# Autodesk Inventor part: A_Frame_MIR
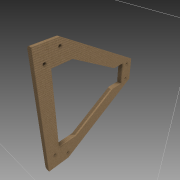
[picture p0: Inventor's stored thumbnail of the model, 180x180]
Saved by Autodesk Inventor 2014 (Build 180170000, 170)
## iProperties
Created: 2013-12
Part Number: A_Frame_MIR
Material: MDF Medium Density Fiberboard
Document SubType Name: Modeling
Designer: Bram
Density: 0.8 g/cm^3
Appearance: Cardboard - Corrugated
Author: Bram
d0: 7,800 ul
d2: 2,800 ul
d4: 4,625 ul
d6: 28,878 ul
d8: 33,300 ul
d10: 35,400 ul
d12: 37,800 ul
d14: 4,045 ul
d16: 2,900 ul
d18: 4,422 ul
d20: 2,400 ul
d22: 5,350 ul
d24: 13,950 ul
d26: 7,019 ul
d28: 21,250 ul
d30: 8,000 ul
d32: 7,300 ul
d34: 18,000 mm
d35: 0,00 deg
d36: 10,000 mm
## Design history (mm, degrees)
derived "A_Frame.ipt"
  sketch "Sketch1"
    geometry: L1 (-303.237, 40.135)-(-5.237, 212.185) reference; L2 (17.986, 139.185)-(-41.677, 139.185) reference; L3 (17.986, 139.185)-(28.513, 139.185) reference; L4 (28.513, 139.185)-(28.513, -0.315) reference; L5 (28.513, 212.185)-(-5.237, 212.185) reference; L6 (-5.237, 212.185)-(74.763, 212.185) reference; L7 (74.763, 212.185)-(74.763, -0.315) reference; L8 (-258.237, 39.685)-(-214.016, 39.685) reference; L9 (-214.016, 39.685)-(-41.677, 139.185) reference; L10 (-303.237, 40.135)-(-303.237, -0.315) reference; L11 (-258.237, 39.685)-(-258.237, -0.315) reference; L12 (-303.237, -40.764)-(-5.237, -212.815) reference; L13 (-214.016, -40.315)-(-41.677, -139.815) reference; L14 (28.513, -139.815)-(28.513, -0.315) reference; L15 (17.986, -139.815)-(-41.677, -139.815) reference; L16 (17.986, -139.815)-(28.513, -139.815) reference; L17 (28.513, -212.815)-(-5.237, -212.815) reference; L18 (-5.237, -212.815)-(74.763, -212.815) reference; L19 (74.763, -212.815)-(74.763, -0.315) reference; L20 (-258.237, -40.315)-(-214.016, -40.315) reference; L21 (-303.237, -40.764)-(-303.237, -0.315) reference; L22 (-258.237, -40.315)-(-258.237, -0.315) reference; L23 (28.513, 139.185)-(-41.677, 139.185) reference; L24 (-41.677, 139.185)-(-214.016, 39.685) reference; L25 (-214.016, 39.685)-(-258.237, 39.685) reference; L26 (-258.237, 39.685)-(-258.237, -40.315) reference; L27 (-258.237, -40.315)-(-214.016, -40.315) reference; L28 (-214.016, -40.315)-(-41.677, -139.815) reference; L29 (-41.677, -139.815)-(28.513, -139.815) reference; L30 (28.513, 139.185)-(28.513, -139.815) reference; L31 (74.763, 212.185)-(-5.237, 212.185) reference; L32 (-5.237, 212.185)-(-303.237, 40.135) reference; L33 (-303.237, 40.135)-(-303.237, -40.764) reference; L34 (-303.237, -40.764)-(-5.237, -212.815) reference; L35 (-5.237, -212.815)-(74.763, -212.815) reference; L36 (74.763, -212.815)-(74.763, 212.185) reference; C1 r 5 at (46.763, 158.685) reference; C2 r 5 at (-3.237, 188.185) reference; C3 r 5 at (-279.237, 28.685) reference; C4 r 5 at (46.763, -159.315) reference; C5 r 5 at (-3.237, -188.815) reference; C6 r 5 at (-279.237, -29.315) reference
feature "Solid1::A_Frame.ipt"
tag "TaggingFeature1"
body "Solid1"
other parameters: "d0" = 1, "d0_1" = 78, "d2" = 2.8, "d4" = 4.625, "d6" = 28.8779, "d8" = 33.3, "d10" = 35.4, "d12" = 37.8, "d14" = 4.04496, "d16" = 2.9, "d18" = 4.42212, "d20" = 2.4, "d22" = 5.35, "d24" = 13.95, "d26" = 7.01897, "d28" = 21.25, "d30" = 8, "d32" = 7.3, "d34" = 18, "d35" = 0 deg, "d36" = 10
